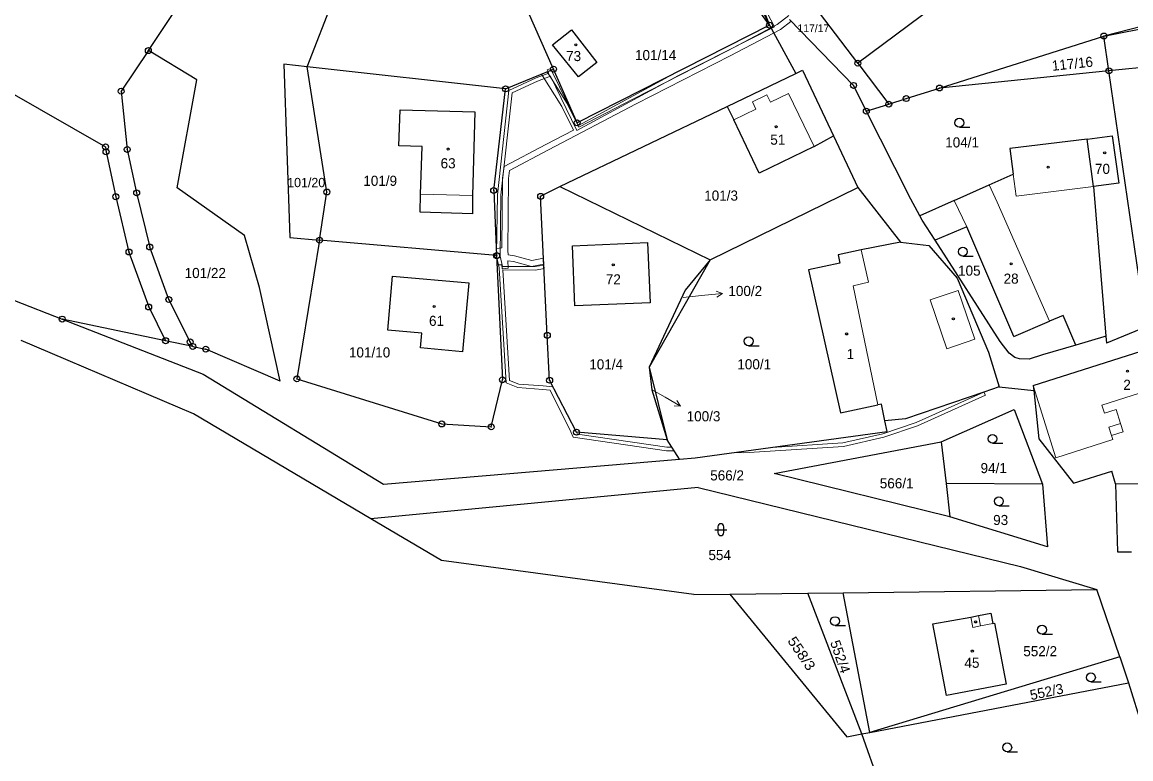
# Model space of a CAD drawing. Extents: x -664548 to -662415, y -1069720 to -1068208.
# Drawn here: x -664002.1 to -663815.4, y -1068905.8 to -1068781.7 of the extents above; entities that cross this region are included whole.
import ezdxf
from ezdxf.enums import TextEntityAlignment as Align

# ---------------------------------------------------------------- set-up
doc = ezdxf.new("R2010")
doc.units = 0
doc.header["$LTSCALE"] = 0.68
for name, color, linetype, lineweight in [('1', 7, 'Continuous', 25), ('13', 7, 'Continuous', 13), ('3', 7, 'Continuous', 25), ('4', 7, 'Continuous', 13), ('5', 7, 'Continuous', 25), ('7', 7, 'Continuous', 13), ('8', 7, 'Continuous', 25)]:
    doc.layers.add(name, color=color, linetype=linetype, lineweight=lineweight)
doc.layers.add('2', color=7, linetype='Continuous')

msp = doc.modelspace()

# ---------------------------------------------------------------- linework, layer by layer
at = {"layer": '1'}
for p, q in [((-663876.25, -1068782.21), (-663892.96, -1068759.02)), ((-663883.22, -1068764.61), (-663876.25, -1068782.21)), ((-663833.18, -1068767.59), (-663861.38, -1068788.6)), ((-663980.88, -1068786.48), (-663970.99, -1068771.67)), ((-663912.63, -1068789.6), (-663919.06, -1068774.98)), ((-663861.38, -1068788.6), (-663872.14, -1068774.44)), ((-663954.1, -1068789.23), (-663949.15, -1068776.44)), ((-663872.89, -1068781.23), (-663862.1, -1068792.34)), ((-663803.43, -1068779.87), (-663819.93, -1068784.02)), ((-663819.93, -1068784.02), (-663803.47, -1068780.79)), ((-663912.83, -1068785.52), (-663909.62, -1068782.98)), ((-663909.62, -1068782.98), (-663905.31, -1068788.47)), ((-663876.25, -1068782.21), (-663908.66, -1068798.64)), ((-663876.25, -1068782.21), (-663871.82, -1068790.35)), ((-663847.62, -1068792.78), (-663819.93, -1068784.02)), ((-663819.08, -1068789.89), (-663819.93, -1068784.02)), ((-663972.73, -1068791.4), (-663980.88, -1068786.48)), ((-663908.4, -1068790.9), (-663912.83, -1068785.52)), ((-663905.31, -1068788.47), (-663908.4, -1068790.9)), ((-663861.38, -1068788.6), (-663856.16, -1068795.49)), ((-663802.69, -1068788.23), (-663819.08, -1068789.89)), ((-663920.7, -1068792.93), (-663954.1, -1068789.23)), ((-663950.81, -1068810.29), (-663954.1, -1068789.23)), ((-663920.7, -1068792.93), (-663912.63, -1068789.6)), ((-663908.66, -1068798.64), (-663912.63, -1068789.6)), ((-663883.41, -1068795.89), (-663871.82, -1068790.35)), ((-663871.82, -1068790.35), (-663870.67, -1068789.8)), ((-663870.67, -1068789.8), (-663865.48, -1068800.81)), ((-663819.08, -1068789.89), (-663847.62, -1068792.78)), ((-663812.8, -1068833.01), (-663819.08, -1068789.89)), ((-663976.03, -1068809.58), (-663972.73, -1068791.4)), ((-663922.71, -1068810.04), (-663920.7, -1068792.93)), ((-663853.23, -1068794.56), (-663847.62, -1068792.78)), ((-663911.57, -1068809.37), (-663883.41, -1068795.89)), ((-663883.41, -1068795.89), (-663882.25, -1068798.13)), ((-663856.16, -1068795.49), (-663853.23, -1068794.56)), ((-663938.66, -1068802.49), (-663938.47, -1068796.43)), ((-663938.47, -1068796.43), (-663925.87, -1068796.81)), ((-663925.87, -1068796.81), (-663926.29, -1068810.89)), ((-663877.97, -1068807.14), (-663882.25, -1068798.13)), ((-663859.95, -1068796.69), (-663852.86, -1068810.79)), ((-663868.75, -1068802.63), (-663865.48, -1068800.81)), ((-663865.48, -1068800.81), (-663861.38, -1068809.51)), ((-663822.74, -1068801.37), (-663835.77, -1068802.97)), ((-663822.74, -1068801.37), (-663818.54, -1068800.82)), ((-663821.66, -1068809.37), (-663822.74, -1068801.37)), ((-663818.54, -1068800.82), (-663817.43, -1068808.8)), ((-663934.77, -1068802.63), (-663938.66, -1068802.49)), ((-663935.02, -1068810.64), (-663934.77, -1068802.63)), ((-663868.75, -1068802.63), (-663877.97, -1068807.14)), ((-663835.77, -1068802.97), (-663835.19, -1068807.29)), ((-663839.23, -1068809.09), (-663835.19, -1068807.29)), ((-663914.8, -1068811.02), (-663911.57, -1068809.37)), ((-663911.57, -1068809.37), (-663886.24, -1068821.71)), ((-663845.15, -1068811.73), (-663839.23, -1068809.09)), ((-663817.43, -1068808.8), (-663821.66, -1068809.37)), ((-663821.66, -1068809.37), (-663819.58, -1068834.55)), ((-663964.68, -1068817.62), (-663976.03, -1068809.58)), ((-663952.04, -1068818.41), (-663950.81, -1068810.29)), ((-663935.08, -1068813.7), (-663935.02, -1068810.64)), ((-663926.29, -1068810.89), (-663926.27, -1068813.98)), ((-663922.71, -1068810.04), (-663922.21, -1068821.01)), ((-663913.68, -1068834.44), (-663914.8, -1068811.02)), ((-663886.24, -1068821.71), (-663861.38, -1068809.51)), ((-663861.38, -1068809.51), (-663854.19, -1068818.75)), ((-663850.92, -1068814.31), (-663852.86, -1068810.79)), ((-663845.15, -1068811.73), (-663850.92, -1068814.31)), ((-663926.27, -1068813.98), (-663935.08, -1068813.7)), ((-663850.52, -1068815.03), (-663850.92, -1068814.31)), ((-663848.35, -1068818.41), (-663850.52, -1068815.03)), ((-663842.99, -1068816.16), (-663848.35, -1068818.41)), ((-663835.08, -1068834.63), (-663842.99, -1068816.16)), ((-663962.18, -1068826.39), (-663964.68, -1068817.62)), ((-663952.04, -1068818.41), (-663955.86, -1068841.77)), ((-663922.21, -1068821.01), (-663952.04, -1068818.41)), ((-663854.19, -1068818.75), (-663860.79, -1068820.03)), ((-663854.19, -1068818.75), (-663849.4, -1068819.31)), ((-663837.39, -1068835.48), (-663848.35, -1068818.41)), ((-663984.14, -1068820.4), (-663980.82, -1068829.66)), ((-663977.43, -1068828.4), (-663980.65, -1068819.56)), ((-663896.79, -1068818.79), (-663896.34, -1068828.97)), ((-663860.79, -1068820.03), (-663864.7, -1068820.89)), ((-663849.4, -1068819.31), (-663844.62, -1068824.8)), ((-663922.21, -1068821.01), (-663921.23, -1068841.92)), ((-663886.24, -1068821.71), (-663896.53, -1068839.78)), ((-663886.24, -1068821.71), (-663890.44, -1068826.85)), ((-663864.7, -1068820.89), (-663864.39, -1068822.26)), ((-663940.53, -1068833.56), (-663939.73, -1068824.47)), ((-663939.73, -1068824.47), (-663926.91, -1068825.62)), ((-663926.91, -1068825.62), (-663927.97, -1068837.2)), ((-663844.62, -1068824.8), (-663839.35, -1068837.27)), ((-663958.67, -1068842.18), (-663962.18, -1068826.39)), ((-663890.44, -1068826.85), (-663896.53, -1068839.78)), ((-664003.45, -1068828.54), (-663995.38, -1068831.7)), ((-663980.82, -1068829.66), (-663977.97, -1068835.34)), ((-663973.85, -1068835.54), (-663977.43, -1068828.4)), ((-663977.97, -1068835.34), (-663995.38, -1068831.7)), ((-663995.38, -1068831.7), (-663971.66, -1068840.98)), ((-663826.8, -1068831.08), (-663829.09, -1068832.06)), ((-663824.68, -1068836.07), (-663826.8, -1068831.08)), ((-663934.81, -1068834.07), (-663940.53, -1068833.56)), ((-663835.08, -1068834.63), (-663829.09, -1068832.06)), ((-663812.8, -1068833.01), (-663819.48, -1068835.77)), ((-663973.25, -1068847.68), (-664002.28, -1068835.3)), ((-663973.4, -1068836.3), (-663977.97, -1068835.34)), ((-663973.4, -1068836.3), (-663973.85, -1068835.54)), ((-663935.06, -1068836.56), (-663934.81, -1068834.07)), ((-663913.29, -1068842), (-663913.68, -1068834.44)), ((-663835.91, -1068837.42), (-663837.39, -1068835.48)), ((-663831.83, -1068842.88), (-663804.77, -1068834.29)), ((-663819.96, -1068834.66), (-663824.68, -1068836.07)), ((-663819.58, -1068834.55), (-663819.96, -1068834.66)), ((-663819.58, -1068834.55), (-663819.48, -1068835.77)), ((-663973.4, -1068836.3), (-663971.2, -1068836.76)), ((-663958.67, -1068842.18), (-663971.2, -1068836.76)), ((-663927.97, -1068837.2), (-663935.06, -1068836.56)), ((-663839.35, -1068837.27), (-663837.56, -1068843.1)), ((-663834.95, -1068838.15), (-663835.91, -1068837.42)), ((-663824.68, -1068836.07), (-663830.26, -1068837.73)), ((-663834.15, -1068838.39), (-663834.95, -1068838.15)), ((-663832.5, -1068838.46), (-663834.15, -1068838.39)), ((-663830.26, -1068837.73), (-663832.5, -1068838.46)), ((-663971.66, -1068840.98), (-663941.25, -1068859.52)), ((-663896.53, -1068839.78), (-663896.09, -1068843.59)), ((-663896.53, -1068839.78), (-663893.49, -1068852.01)), ((-663955.86, -1068841.77), (-663931.45, -1068849.36)), ((-663923.13, -1068849.85), (-663921.23, -1068841.92)), ((-663908.76, -1068850.76), (-663913.29, -1068842)), ((-663831.83, -1068842.88), (-663831.74, -1068843.7)), ((-663896.09, -1068843.59), (-663893.49, -1068852.01)), ((-663840.15, -1068843.99), (-663853.34, -1068848.5)), ((-663837.56, -1068843.1), (-663840.15, -1068843.99)), ((-663837.56, -1068843.1), (-663831.74, -1068843.7)), ((-663831.74, -1068843.7), (-663830.88, -1068851.88)), ((-663864.32, -1068847.51), (-663858.03, -1068846.16)), ((-663857.39, -1068846.02), (-663858.03, -1068846.16)), ((-663856.82, -1068848.81), (-663857.39, -1068846.02)), ((-663943.4, -1068865.32), (-663973.25, -1068847.68)), ((-663853.34, -1068848.5), (-663856.82, -1068848.81)), ((-663847.32, -1068852.35), (-663835.05, -1068846.95)), ((-663835.05, -1068846.95), (-663830.26, -1068859.5)), ((-663931.45, -1068849.36), (-663923.13, -1068849.85)), ((-663856.44, -1068850.64), (-663856.82, -1068848.81)), ((-663893.49, -1068852.01), (-663908.76, -1068850.76)), ((-663891.41, -1068855.3), (-663893.49, -1068852.01)), ((-663888.77, -1068855.08), (-663856.44, -1068850.64)), ((-663875.45, -1068857.68), (-663847.32, -1068852.35)), ((-663847.32, -1068852.35), (-663846.52, -1068859.39)), ((-663830.88, -1068851.88), (-663825.07, -1068859.35)), ((-663941.25, -1068859.52), (-663891.41, -1068855.3)), ((-663891.41, -1068855.3), (-663888.77, -1068855.08)), ((-663845.87, -1068865.03), (-663875.45, -1068857.68)), ((-663825.07, -1068859.35), (-663818.6, -1068857.34)), ((-663817.97, -1068859.47), (-663818.6, -1068857.34)), ((-663830.26, -1068859.5), (-663846.52, -1068859.39)), ((-663846.52, -1068859.39), (-663845.87, -1068865.03)), ((-663830.26, -1068859.5), (-663829.45, -1068870.08)), ((-663817.97, -1068859.47), (-663817.66, -1068870.91)), ((-663888.25, -1068860.09), (-663943.4, -1068865.32)), ((-663888.25, -1068860.09), (-663834, -1068873.39)), ((-663931.49, -1068872.36), (-663943.4, -1068865.32)), ((-663829.45, -1068870.08), (-663845.87, -1068865.03)), ((-663817.66, -1068870.91), (-663815.28, -1068870.91)), ((-663889.01, -1068878.11), (-663931.49, -1068872.36)), ((-663834, -1068873.39), (-663821.13, -1068877.25)), ((-663889.01, -1068878.11), (-663882.96, -1068878.05)), ((-663882.96, -1068878.05), (-663869.81, -1068877.88)), ((-663882.96, -1068878.05), (-663863.21, -1068902.04)), ((-663869.81, -1068877.88), (-663863.85, -1068877.8)), ((-663860.72, -1068901.56), (-663869.81, -1068877.88)), ((-663863.85, -1068877.8), (-663821.13, -1068877.25)), ((-663859.38, -1068901.31), (-663863.85, -1068877.8)), ((-663817.26, -1068888.61), (-663821.13, -1068877.25)), ((-663848.73, -1068883.02), (-663842.35, -1068881.88)), ((-663842.35, -1068881.88), (-663841.05, -1068881.63)), ((-663841.05, -1068881.63), (-663838.96, -1068881.23)), ((-663838.96, -1068881.23), (-663838.63, -1068882.97)), ((-663846.42, -1068895.1), (-663848.73, -1068883.02)), ((-663838.63, -1068882.97), (-663838.38, -1068882.92)), ((-663838.38, -1068882.92), (-663836.42, -1068893.18)), ((-663817.26, -1068888.61), (-663859.38, -1068901.31)), ((-663817.26, -1068888.61), (-663815.78, -1068892.97)), ((-663859.38, -1068901.31), (-663815.78, -1068892.97)), ((-663836.42, -1068893.18), (-663846.42, -1068895.1)), ((-663815.78, -1068892.97), (-663810.81, -1068909.09)), ((-663863.21, -1068902.04), (-663860.72, -1068901.56)), ((-663860.72, -1068901.56), (-663859.38, -1068901.31)), ((-663855.38, -1068916.4), (-663860.72, -1068901.56))]:
    msp.add_line(p, q, dxfattribs=at)
for points in [[(-664015.89, -1068786.78), (-663988.08, -1068802.69), (-663988, -1068803.53), (-663986.36, -1068811.09), (-663984.14, -1068820.4)], [(-663980.88, -1068786.48), (-663985.46, -1068793.32), (-663984.43, -1068803.13)], [(-663954.1, -1068789.23), (-663958.08, -1068788.79), (-663957.02, -1068817.97), (-663952.04, -1068818.41)], [(-663862.1, -1068792.34), (-663859.95, -1068796.69), (-663856.16, -1068795.49)], [(-663984.43, -1068803.13), (-663982.85, -1068810.44), (-663980.65, -1068819.56)], [(-663896.34, -1068828.97), (-663909.03, -1068829.49), (-663909.43, -1068819.34), (-663896.79, -1068818.79)], [(-663864.39, -1068822.26), (-663869.67, -1068823.42), (-663864.32, -1068847.51)]]:
    msp.add_lwpolyline(points, dxfattribs=at)
at = {"layer": '13'}
for points in [[(-663877.8, -1068779.16), (-663876.25, -1068782.21), (-663891.88, -1068790.13), (-663908.43, -1068799.12), (-663908.66, -1068798.64), (-663913.14, -1068789.49), (-663913.7, -1068789.72), (-663913.43, -1068790.26), (-663915.57, -1068791.05), (-663920.18, -1068793.21), (-663922.08, -1068810.78), (-663922.22, -1068820.71), (-663922.52, -1068820.68), (-663922.49, -1068821.29), (-663922.2, -1068821.31), (-663921.77, -1068823.05), (-663920.63, -1068842.43), (-663918.64, -1068843.23), (-663914.45, -1068843.55), (-663913.21, -1068843.65), (-663909.73, -1068850.7), (-663909.3, -1068851.58), (-663893.6, -1068853.86), (-663892.3, -1068853.89), (-663892.68, -1068853.28), (-663893.55, -1068853.26), (-663908.6, -1068851.07), (-663908.76, -1068850.76), (-663912.73, -1068843.09), (-663914.4, -1068842.96), (-663918.5, -1068842.64), (-663920.05, -1068842.02), (-663921.15, -1068823.43), (-663915.65, -1068823.44), (-663914.22, -1068823.2), (-663914.25, -1068822.59), (-663915.7, -1068822.84), (-663921.21, -1068822.83), (-663921.63, -1068821.1), (-663921.48, -1068810.81), (-663919.62, -1068793.61), (-663915.33, -1068791.61), (-663913.16, -1068790.8), (-663908.69, -1068799.94), (-663891.6, -1068790.66), (-663875.44, -1068782.47), (-663877.3, -1068778.81)], [(-663872.99, -1068780.56), (-663874.98, -1068782.06), (-663883.34, -1068786.49), (-663899.16, -1068794.59), (-663908.39, -1068799.4), (-663910.35, -1068795.4), (-663913.72, -1068790.05), (-663914.67, -1068790.44), (-663911.23, -1068795.88), (-663909.27, -1068799.86), (-663913.91, -1068802.31), (-663920.95, -1068806.02), (-663921.2, -1068807.94), (-663921.33, -1068819.71), (-663922.26, -1068819.83), (-663922.21, -1068821.01), (-663922.14, -1068822.58), (-663921.34, -1068822.55), (-663921.29, -1068823.23), (-663920.29, -1068823.14), (-663920.35, -1068821.89), (-663919.38, -1068822.01), (-663916.33, -1068822.85), (-663914.25, -1068822.46), (-663914.3, -1068821.46), (-663916.29, -1068821.82), (-663919.18, -1068821.02), (-663920.29, -1068820.89), (-663920.33, -1068820.13), (-663920.2, -1068808), (-663920.03, -1068806.66), (-663913.47, -1068803.17), (-663898.7, -1068795.47), (-663882.88, -1068787.37), (-663874.43, -1068782.9), (-663872.66, -1068781.56)]]:
    msp.add_lwpolyline(points, dxfattribs=at)
msp.add_lwpolyline([(-663840.15, -1068843.99), (-663851.53, -1068849.13), (-663857.14, -1068851.03), (-663863.88, -1068852.55), (-663875.88, -1068853.31), (-663882.12, -1068854.17), (-663880.56, -1068854.21), (-663863.8, -1068853.15), (-663856.98, -1068851.61), (-663851.31, -1068849.69), (-663839.9, -1068844.53)], close=True, dxfattribs=at)
at = {"layer": '3'}
for p, q in [((-663844.273, -1068799.38), (-663842.523, -1068799.38)), ((-663843.693, -1068821.1), (-663841.943, -1068821.1)), ((-663879.773, -1068836.18), (-663878.023, -1068836.18)), ((-663838.693, -1068852.62), (-663836.943, -1068852.62)), ((-663837.623, -1068863.13), (-663835.873, -1068863.13)), ((-663885.461, -1068867.171), (-663883.459, -1068867.171)), ((-663884.961, -1068866.671), (-663884.961, -1068867.672)), ((-663883.959, -1068867.672), (-663883.959, -1068866.671)), ((-663865.213, -1068883.32), (-663863.463, -1068883.32)), ((-663830.353, -1068884.77), (-663828.603, -1068884.77)), ((-663822.123, -1068892.8), (-663820.373, -1068892.8)), ((-663836.213, -1068904.59), (-663834.463, -1068904.59))]:
    msp.add_line(p, q, dxfattribs=at)
for centre in [(-663844.2729, -1068798.6298), (-663843.6929, -1068820.3498), (-663879.7729, -1068835.4298), (-663838.6929, -1068851.8698), (-663837.6229, -1068862.3798), (-663865.2129, -1068882.5698), (-663830.3529, -1068884.0198), (-663822.1229, -1068892.0498), (-663836.2129, -1068903.8398)]:
    msp.add_circle(centre, 0.75, dxfattribs=at)
for centre, start, end in [((-663884.46, -1068866.6709), 0, 180), ((-663884.46, -1068867.6709), 180, 359.98789)]:
    msp.add_arc(centre, 0.5, start, end, dxfattribs=at)
at = {"layer": '4'}
for p, q in [((-663879.13, -1068795.13), (-663876.68, -1068793.95)), ((-663876.68, -1068793.95), (-663876.08, -1068795.16)), ((-663876.08, -1068795.16), (-663873.06, -1068793.71)), ((-663868.75, -1068802.63), (-663873.06, -1068793.71)), ((-663882.25, -1068798.13), (-663878.55, -1068796.35)), ((-663878.55, -1068796.35), (-663879.13, -1068795.13)), ((-663834.69, -1068811.01), (-663835.19, -1068807.29)), ((-663839.23, -1068809.09), (-663837.88, -1068812)), ((-663821.66, -1068809.37), (-663834.69, -1068811.01)), ((-663935.02, -1068810.64), (-663926.29, -1068810.89)), ((-663842.99, -1068816.16), (-663845.15, -1068811.73)), ((-663837.88, -1068812), (-663829.09, -1068832.06)), ((-663859.59, -1068825.5), (-663860.79, -1068820.03)), ((-663862.17, -1068826.07), (-663859.59, -1068825.5)), ((-663858.03, -1068846.16), (-663862.17, -1068826.07)), ((-663849.19, -1068828.46), (-663844.46, -1068826.86)), ((-663831.83, -1068842.88), (-663828.02, -1068855.04)), ((-663820.26, -1068846.18), (-663808.81, -1068842.54)), ((-663819.83, -1068847.53), (-663820.26, -1068846.18)), ((-663819.83, -1068847.53), (-663817.87, -1068846.91)), ((-663817.87, -1068846.91), (-663817.12, -1068849.28)), ((-663817.12, -1068849.28), (-663819.08, -1068849.9)), ((-663819.08, -1068849.9), (-663818.63, -1068851.3)), ((-663816.67, -1068850.68), (-663817.12, -1068849.28)), ((-663828.02, -1068855.04), (-663818.42, -1068851.97)), ((-663818.63, -1068851.3), (-663816.67, -1068850.68)), ((-663818.42, -1068851.97), (-663818.63, -1068851.3)), ((-663810.87, -1068859.45), (-663817.97, -1068859.47)), ((-663842.35, -1068881.88), (-663842.02, -1068883.62)), ((-663842.02, -1068883.62), (-663840.72, -1068883.37))]:
    msp.add_line(p, q, dxfattribs=at)
for points in [[(-663849.19, -1068828.46), (-663846.4, -1068836.7), (-663841.67, -1068835.1), (-663844.46, -1068826.86)], [(-663841.05, -1068881.63), (-663840.72, -1068883.37), (-663838.63, -1068882.97)]]:
    msp.add_lwpolyline(points, dxfattribs=at)
at = {"layer": '5'}
for centre in [(-663908.8868, -1068785.5092), (-663875.1368, -1068799.2992), (-663930.3668, -1068803.0592), (-663819.7968, -1068803.6992), (-663829.3068, -1068806.1192), (-663902.5668, -1068822.5692), (-663835.5568, -1068822.3892), (-663932.7468, -1068829.5792), (-663845.2868, -1068831.6392), (-663863.2668, -1068834.1992), (-663815.9668, -1068840.4692), (-663841.5368, -1068882.7092), (-663842.0968, -1068887.6092)]:
    msp.add_circle(centre, 0.175, dxfattribs=at)
at = {"layer": '7'}
for p, q in [((-663884.185, -1068827.376), (-663885.234, -1068826.983)), ((-663891.221, -1068846.37), (-663891.838, -1068845.436))]:
    msp.add_line(p, q, dxfattribs=at)
for points in [[(-663890.78, -1068828.05), (-663887.17, -1068827.69), (-663884.185, -1068827.376), (-663885.129, -1068827.979)], [(-663896.02, -1068843.62), (-663893.82, -1068844.87), (-663891.221, -1068846.37), (-663892.339, -1068846.303)]]:
    msp.add_lwpolyline(points, dxfattribs=at)
at = {"layer": '8'}
for centre, radius in [((-663876.25, -1068782.2099), 0.5), ((-663876.25, -1068782.2099), 0.0303), ((-663819.93, -1068784.0199), 0.5), ((-663819.93, -1068784.0199), 0.0303), ((-663980.88, -1068786.4799), 0.5), ((-663980.88, -1068786.4799), 0.0303), ((-663861.3799, -1068788.5999), 0.5), ((-663861.3799, -1068788.5999), 0.0303), ((-663912.63, -1068789.5999), 0.5), ((-663912.63, -1068789.5999), 0.0303), ((-663819.0799, -1068789.8899), 0.5), ((-663819.0799, -1068789.8899), 0.0303), ((-663920.7, -1068792.9299), 0.5), ((-663862.0999, -1068792.3399), 0.5), ((-663862.0999, -1068792.3399), 0.0303), ((-663847.62, -1068792.7799), 0.5), ((-663985.46, -1068793.3199), 0.5), ((-663985.46, -1068793.3199), 0.0303), ((-663920.7, -1068792.9299), 0.0303), ((-663853.2299, -1068794.5599), 0.5), ((-663847.62, -1068792.7799), 0.0303), ((-663859.9499, -1068796.6899), 0.5), ((-663856.1599, -1068795.4899), 0.5), ((-663856.1599, -1068795.4899), 0.0303), ((-663853.2299, -1068794.5599), 0.0303), ((-663908.66, -1068798.6399), 0.5), ((-663859.9499, -1068796.6899), 0.0303), ((-663908.66, -1068798.6399), 0.0303), ((-663988.08, -1068802.6899), 0.5), ((-663988, -1068803.5299), 0.5), ((-663988.08, -1068802.6899), 0.0303), ((-663988, -1068803.5299), 0.0303), ((-663984.43, -1068803.1299), 0.5), ((-663984.43, -1068803.1299), 0.0303), ((-663986.36, -1068811.0899), 0.5), ((-663986.36, -1068811.0899), 0.0303), ((-663982.85, -1068810.4399), 0.5), ((-663982.85, -1068810.4399), 0.0303), ((-663950.81, -1068810.2899), 0.5), ((-663950.81, -1068810.2899), 0.0303), ((-663922.71, -1068810.0399), 0.5), ((-663922.71, -1068810.0399), 0.0303), ((-663914.8, -1068811.0199), 0.5), ((-663914.8, -1068811.0199), 0.0303), ((-663952.04, -1068818.4099), 0.5), ((-663952.04, -1068818.4099), 0.0303), ((-663984.14, -1068820.3999), 0.5), ((-663984.14, -1068820.3999), 0.0303), ((-663980.65, -1068819.5599), 0.5), ((-663980.65, -1068819.5599), 0.0303), ((-663922.21, -1068821.0099), 0.5), ((-663922.21, -1068821.0099), 0.0303), ((-663977.43, -1068828.3999), 0.5), ((-663980.82, -1068829.6599), 0.5), ((-663980.82, -1068829.6599), 0.0303), ((-663977.43, -1068828.3999), 0.0303), ((-663995.38, -1068831.6999), 0.5), ((-663995.38, -1068831.6999), 0.0303), ((-663977.97, -1068835.3399), 0.5), ((-663977.97, -1068835.3399), 0.0303), ((-663973.85, -1068835.5399), 0.5), ((-663973.85, -1068835.5399), 0.0303), ((-663913.68, -1068834.4399), 0.5), ((-663913.68, -1068834.4399), 0.0303), ((-663973.4, -1068836.2999), 0.5), ((-663973.4, -1068836.2999), 0.0303), ((-663971.2, -1068836.7599), 0.5), ((-663971.2, -1068836.7599), 0.0303), ((-663955.86, -1068841.7699), 0.5), ((-663955.86, -1068841.7699), 0.0303), ((-663921.23, -1068841.9199), 0.5), ((-663921.23, -1068841.9199), 0.0303), ((-663913.29, -1068841.9999), 0.5), ((-663913.29, -1068841.9999), 0.0303), ((-663931.45, -1068849.3599), 0.5), ((-663931.45, -1068849.3599), 0.0303), ((-663923.13, -1068849.8499), 0.5), ((-663923.13, -1068849.8499), 0.0303), ((-663908.76, -1068850.7599), 0.5), ((-663908.76, -1068850.7599), 0.0303)]:
    msp.add_circle(centre, radius, dxfattribs=at)

# ---------------------------------------------------------------- texts
at = {"layer": '2'}
for s, height, p in [('117/17', 1.309, (-663868.87, -1068783.367)), ('73', 1.7, (-663909.249, -1068788.245)), ('70', 1.7, (-663820.169, -1068807.245)), ('101/20', 1.564, (-663954.29, -1068809.481)), ('101/22', 1.7, (-663971.29, -1068824.785)), ('72', 1.7, (-663902.559, -1068825.854)), ('105', 1.7, (-663842.599, -1068824.385))]:
    msp.add_text(s, height=height, dxfattribs=at).set_placement(p, align=Align.CENTER)
for s, p in [('101/14', (-663898.91, -1068788.084)), ('51', (-663876.12, -1068802.334)), ('104/1', (-663846.66, -1068802.785)), ('63', (-663931.65, -1068806.304)), ('101/9', (-663944.67, -1068809.255)), ('101/3', (-663887.25, -1068811.745)), ('28', (-663836.82, -1068825.735)), ('100/2', (-663883.18, -1068827.814)), ('61', (-663933.6, -1068832.844)), ('101/10', (-663947.09, -1068838.155)), ('1', (-663863.26, -1068838.435)), ('101/4', (-663906.61, -1068840.175)), ('100/1', (-663881.67, -1068840.155)), ('2', (-663816.66, -1068843.615)), ('100/3', (-663890.21, -1068848.915)), ('94/1', (-663840.7, -1068857.645)), ('566/2', (-663886.24, -1068858.875)), ('566/1', (-663857.68, -1068860.205)), ('93', (-663838.58, -1068866.385)), ('554', (-663886.54, -1068872.295)), ('552/2', (-663833.51, -1068888.485)), ('45', (-663843.42, -1068890.435))]:
    msp.add_text(s, height=1.7, dxfattribs=at).set_placement(p)
msp.add_text('117/16', height=1.7, rotation=6, dxfattribs=at).set_placement((-663825.1493, -1068789.5279), align=Align.CENTER)
at = {"layer": '2', "width": 1.1}
msp.add_text('558/3', height=1.7, rotation=304, dxfattribs=at).set_placement((-663873.302, -1068885.897))
at = {"layer": '2'}
for s, rotation, p in [('552/4', 289, (-663866.071, -1068886.138)), ('552/3', 12, (-663832.181, -1068895.895))]:
    msp.add_text(s, height=1.7, rotation=rotation, dxfattribs=at).set_placement(p)

doc.saveas('drawing.dxf')
